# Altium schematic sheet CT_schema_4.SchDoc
size 284 x 245 mm
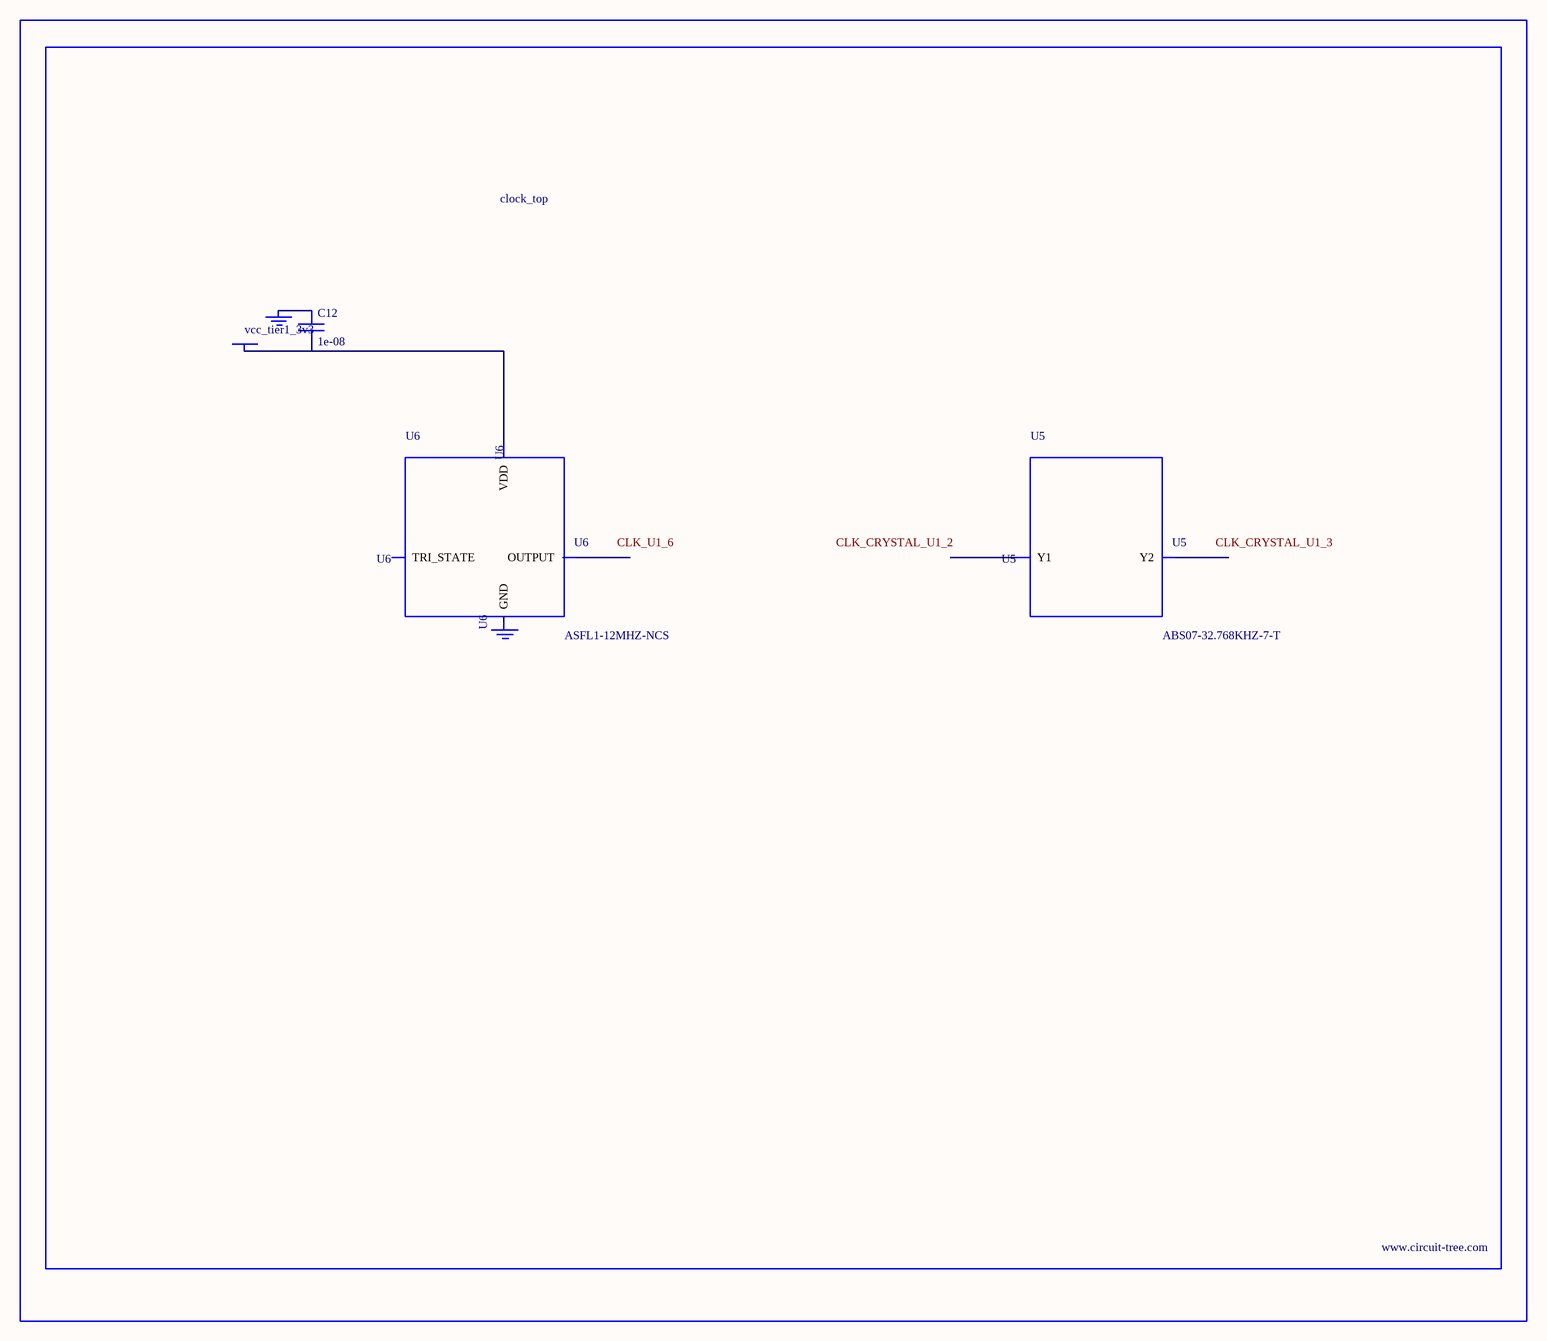
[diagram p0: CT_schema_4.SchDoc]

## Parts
BORDER3  (no value)
C12  1e-08  [C0402]
GND_INSTANCE_3_0  (no value)
GND_INSTANCE_3_1  (no value)
POWER_INSTANCE_3_0  vcc_tier1_3v3
U5  ABS07-32.768KHZ-7-T  [ABS07-32.768KHZ-7-T]
U6  ASFL1-12MHZ-NCS  [ASFL1]

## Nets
NetC12_1: C12.1 GND_INSTANCE_3_0.0(GND)
NetC12_2: C12.2 POWER_INSTANCE_3_0.0(PWR) U6.4(VDD)

Not connected (* = marked no-connect by the designer): GND_INSTANCE_3_1 0(GND); U5 1(Y1) 2(Y2); U6 1(TRI_STATE) 2(GND) 3(OUTPUT)

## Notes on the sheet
- Labels drawn without touching a wire or pin: CLK_CRYSTAL_U1_2, CLK_CRYSTAL_U1_3, CLK_U1_6

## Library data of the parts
BORDER3 = BORDER_PAGE3
C12 = C0402C103K3RAC
GND_INSTANCE_3_0 GND_INSTANCE_3_1 = GND
POWER_INSTANCE_3_0 = PWR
